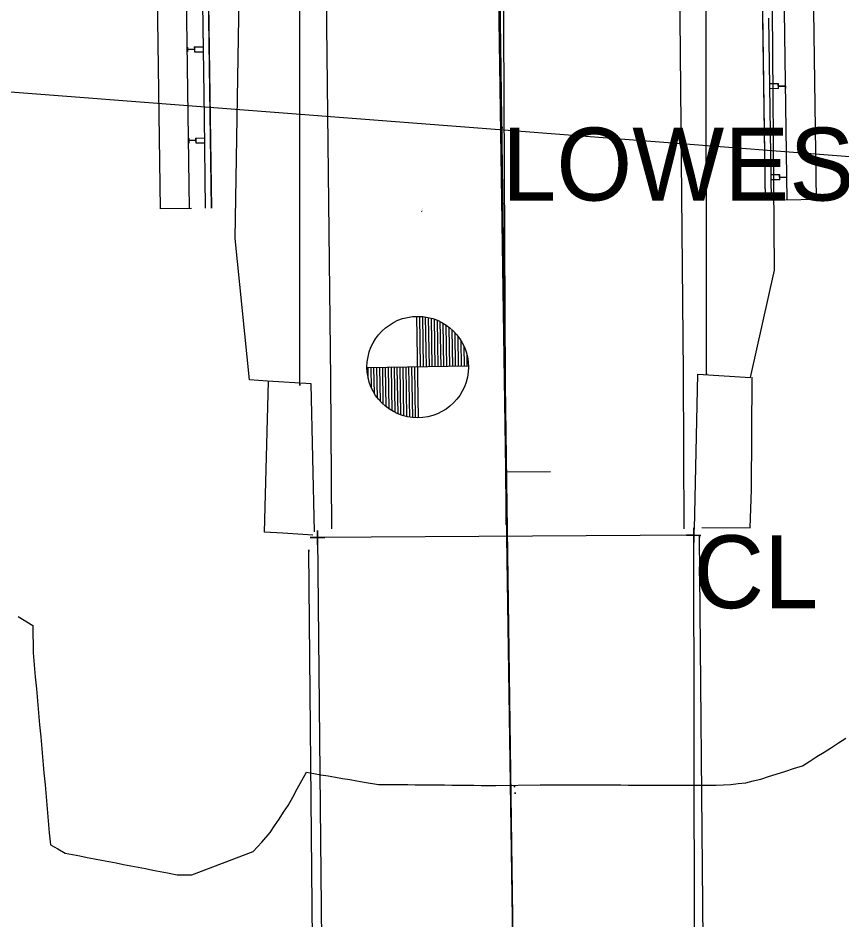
# Model space of a CAD drawing. Extents: x 1674300 to 1677920, y 225056 to 231852.
# Drawn here: x 1677341.1 to 1677397.6, y 229147 to 229208.9 of the extents above; entities that cross this region are included whole.
import ezdxf

# ---------------------------------------------------------------- set-up
doc = ezdxf.new("R2010")
doc.units = 0
for name, color, linetype in [('R_BoreHole', 7, 'Continuous'), ('R_Draft', 7, 'Continuous'), ('R_Horz Alg', 7, 'Continuous'), ('R_Horz Alg Annot', 7, 'Continuous'), ('R_No Plot', 7, 'Continuous'), ('R_Proposed Const Limits_Cut', 7, 'Continuous'), ('R_Proposed Road_Shoulder', 7, 'Continuous'), ('R_Steel', 7, 'Continuous'), ('S_BRIDGE', 7, 'Continuous'), ('S_BRIDGE_ANNOT', 7, 'Continuous'), ('S_EDGE_CONCRETE', 7, 'Continuous'), ('S_EDGE_PAVEMENT', 7, 'Continuous'), ('S_ELECTRIC_UTILITIES', 7, 'Continuous'), ('S_ELECTRIC_UTILITIES_ANNOT', 7, 'Continuous'), ('S_EXISTING_ALIGNMENT', 7, 'Continuous'), ('S_GUARDRAIL', 7, 'Continuous'), ('S_MSC_PT_SYM', 7, 'Continuous'), ('S_PAVEMENT_CROWN', 7, 'Continuous'), ('S_RDW_PT_SYM', 7, 'Continuous'), ('S_SHOULDER', 7, 'Continuous'), ('S_STR_PT_SYM', 7, 'Continuous'), ('S_UTL_PT_SYM', 7, 'Continuous')]:
    doc.layers.add(name, color=color, linetype=linetype)

msp = doc.modelspace()

# ---------------------------------------------------------------- linework, layer by layer
at = {"layer": 'R_BoreHole'}
for p, q in [((1677368.591, 229181.491), (1677368.475, 229188.447)), ((1677368.733, 229184.972), (1677368.675, 229188.451)), ((1677368.933, 229184.976), (1677368.876, 229188.431)), ((1677369.133, 229184.979), (1677369.076, 229188.405)), ((1677369.333, 229184.982), (1677369.277, 229188.367)), ((1677369.533, 229184.986), (1677369.478, 229188.317)), ((1677369.733, 229184.989), (1677369.679, 229188.254)), ((1677369.933, 229184.992), (1677369.88, 229188.176)), ((1677370.133, 229184.996), (1677370.082, 229188.084)), ((1677370.333, 229184.999), (1677370.283, 229187.975)), ((1677370.533, 229185.002), (1677370.486, 229187.848)), ((1677370.733, 229185.005), (1677370.688, 229187.7)), ((1677370.933, 229185.009), (1677370.891, 229187.527)), ((1677371.133, 229185.012), (1677371.094, 229187.323)), ((1677371.333, 229185.015), (1677371.298, 229187.079)), ((1677371.533, 229185.019), (1677371.503, 229186.78)), ((1677371.733, 229185.022), (1677371.71, 229186.386)), ((1677371.933, 229185.025), (1677371.92, 229185.761)), ((1677372.011, 229185.027), (1677365.055, 229184.911)), ((1677365.146, 229184.177), (1677365.133, 229184.913)), ((1677365.356, 229183.552), (1677365.333, 229184.916)), ((1677365.563, 229183.158), (1677365.533, 229184.919)), ((1677365.768, 229182.859), (1677365.733, 229184.923)), ((1677365.972, 229182.615), (1677365.933, 229184.926)), ((1677366.175, 229182.411), (1677366.133, 229184.929)), ((1677366.378, 229182.238), (1677366.333, 229184.933)), ((1677366.58, 229182.09), (1677366.533, 229184.936)), ((1677366.783, 229181.963), (1677366.733, 229184.939)), ((1677366.984, 229181.854), (1677366.933, 229184.942)), ((1677367.186, 229181.762), (1677367.133, 229184.946)), ((1677367.387, 229181.684), (1677367.333, 229184.949)), ((1677367.588, 229181.621), (1677367.533, 229184.952)), ((1677367.789, 229181.571), (1677367.733, 229184.956)), ((1677367.99, 229181.533), (1677367.933, 229184.959)), ((1677368.19, 229181.507), (1677368.133, 229184.962)), ((1677368.391, 229181.493), (1677368.333, 229184.966))]:
    msp.add_line(p, q, dxfattribs=at)
msp.add_circle((1677368.533, 229184.969), 3.479, dxfattribs=at)
at = {"layer": 'R_Horz Alg'}
msp.add_line((1677377.014, 229008.911), (1677360.581, 230177.652), dxfattribs=at)
at = {"layer": 'R_Horz Alg Annot'}
msp.add_lwpolyline([(1677377.64, 229177.793), (1677374.64, 229177.751)], dxfattribs=at)
at = {"layer": 'R_No Plot'}
for points in [[(1677392.38, 229196.403), (1677391.765, 229240.148), (1677391.304, 229415.159)], [(1677354.384, 229195.868), (1677353.768, 229239.614), (1677349.308, 229414.569)]]:
    msp.add_lwpolyline(points, dxfattribs=at)
at = {"layer": 'R_Proposed Const Limits_Cut'}
msp.add_lwpolyline([(1677341.122, 229167.849), (1677342.131, 229167.238), (1677342.139, 229166.613), (1677342.148, 229165.989), (1677342.157, 229165.364), (1677342.231, 229164.541), (1677342.305, 229163.718), (1677342.379, 229162.895), (1677342.453, 229162.072), (1677342.527, 229161.249), (1677342.601, 229160.426), (1677342.675, 229159.603), (1677342.749, 229158.78), (1677342.824, 229157.957), (1677342.898, 229157.134), (1677342.972, 229156.311), (1677343.046, 229155.488), (1677343.12, 229154.665), (1677343.194, 229153.842), (1677343.268, 229153.019), (1677343.342, 229152.196), (1677343.846, 229151.912), (1677344.35, 229151.628), (1677344.852, 229151.532), (1677345.353, 229151.435), (1677345.854, 229151.339), (1677346.356, 229151.242), (1677346.857, 229151.145), (1677347.359, 229151.049), (1677347.86, 229150.952), (1677348.361, 229150.856), (1677348.863, 229150.759), (1677349.364, 229150.662), (1677349.866, 229150.566), (1677350.367, 229150.469), (1677350.868, 229150.373), (1677351.37, 229150.276), (1677352.038, 229150.147), (1677352.541, 229150.14), (1677353.044, 229150.133), (1677357.258, 229151.733), (1677357.837, 229152.384), (1677358.416, 229153.035), (1677358.722, 229153.499), (1677359.028, 229153.963), (1677359.334, 229154.427), (1677359.64, 229154.891), (1677359.958, 229155.461), (1677360.276, 229156.031), (1677360.595, 229156.601), (1677360.913, 229157.171), (1677361.406, 229157.087), (1677361.9, 229157.003), (1677362.394, 229156.919), (1677362.887, 229156.835), (1677363.381, 229156.751), (1677363.874, 229156.668), (1677364.368, 229156.584), (1677364.862, 229156.5), (1677365.851, 229156.347), (1677366.353, 229156.342), (1677366.856, 229156.337), (1677367.359, 229156.332), (1677367.862, 229156.327), (1677368.365, 229156.322), (1677368.867, 229156.317), (1677369.37, 229156.312), (1677369.873, 229156.307), (1677370.376, 229156.302), (1677370.879, 229156.297), (1677371.382, 229156.292), (1677371.884, 229156.287), (1677372.387, 229156.282), (1677372.89, 229156.277), (1677373.393, 229156.272), (1677373.896, 229156.267), (1677376.922, 229156.317), (1677377.425, 229156.316), (1677377.928, 229156.314), (1677378.432, 229156.313), (1677378.935, 229156.312), (1677379.438, 229156.31), (1677379.941, 229156.309), (1677380.445, 229156.308), (1677380.948, 229156.306), (1677381.451, 229156.305), (1677381.954, 229156.303), (1677382.457, 229156.302), (1677382.961, 229156.301), (1677383.464, 229156.299), (1677383.967, 229156.298), (1677384.47, 229156.297), (1677384.974, 229156.295), (1677385.477, 229156.294), (1677385.98, 229156.293), (1677386.483, 229156.291), (1677386.987, 229156.29), (1677387.49, 229156.288), (1677387.993, 229156.287), (1677388.496, 229156.286), (1677389, 229156.284), (1677389.506, 229156.312), (1677390.013, 229156.339), (1677390.523, 229156.394), (1677391.032, 229156.45), (1677391.551, 229156.581), (1677392.07, 229156.711), (1677392.593, 229156.879), (1677393.116, 229157.047), (1677393.781, 229157.261), (1677394.303, 229157.428), (1677394.922, 229157.627), (1677395.418, 229157.938), (1677395.914, 229158.249), (1677396.409, 229158.564), (1677396.905, 229158.879), (1677397.401, 229159.194), (1677397.896, 229159.509)], dxfattribs=at)
at = {"layer": 'R_Proposed Road_Shoulder'}
for p, q in [((1677395.879, 229196.452), (1677393.755, 229196.422)), ((1677353.009, 229195.849), (1677350.884, 229195.819))]:
    msp.add_line(p, q, dxfattribs=at)
for points in [[(1677395.879, 229196.452), (1677395.264, 229240.197), (1677394.804, 229415.208), (1677394.663, 229425.207), (1677388.7, 229458.127)], [(1677350.884, 229195.819), (1677350.269, 229239.565), (1677345.809, 229414.519), (1677345.668, 229424.518), (1677350.704, 229457.592)]]:
    msp.add_lwpolyline(points, dxfattribs=at)
at = {"layer": 'R_Steel'}
for p, q in [((1677352.728, 229206.918), (1677352.744, 229206.918)), ((1677353.213, 229206.925), (1677353.228, 229206.925)), ((1677353.228, 229206.925), (1677353.811, 229206.933)), ((1677352.733, 229206.585), (1677352.749, 229206.585)), ((1677353.207, 229206.766), (1677352.754, 229206.759)), ((1677353.208, 229206.75), (1677352.755, 229206.743)), ((1677353.218, 229206.592), (1677353.233, 229206.592)), ((1677353.233, 229206.592), (1677353.816, 229206.6)), ((1677393.767, 229204.414), (1677393.751, 229204.413)), ((1677393.267, 229204.407), (1677392.684, 229204.398)), ((1677393.272, 229204.074), (1677392.689, 229204.065)), ((1677393.282, 229204.407), (1677393.267, 229204.407)), ((1677393.287, 229204.074), (1677393.272, 229204.074)), ((1677393.293, 229204.249), (1677393.746, 229204.255)), ((1677393.293, 229204.233), (1677393.746, 229204.239)), ((1677393.772, 229204.081), (1677393.756, 229204.08)), ((1677352.816, 229200.667), (1677352.832, 229200.668)), ((1677352.821, 229200.334), (1677352.837, 229200.335)), ((1677353.295, 229200.515), (1677352.842, 229200.509)), ((1677353.295, 229200.499), (1677352.842, 229200.493)), ((1677353.301, 229200.674), (1677353.316, 229200.674)), ((1677353.306, 229200.341), (1677353.321, 229200.341)), ((1677353.316, 229200.674), (1677353.899, 229200.683)), ((1677353.321, 229200.341), (1677353.904, 229200.35)), ((1677393.355, 229198.156), (1677392.772, 229198.148)), ((1677393.36, 229197.823), (1677392.777, 229197.815)), ((1677393.37, 229198.156), (1677393.355, 229198.156)), ((1677393.375, 229197.823), (1677393.36, 229197.823)), ((1677393.38, 229197.998), (1677393.833, 229198.005)), ((1677393.381, 229197.982), (1677393.834, 229197.989)), ((1677393.855, 229198.163), (1677393.839, 229198.163)), ((1677393.86, 229197.83), (1677393.844, 229197.83))]:
    msp.add_line(p, q, dxfattribs=at)
for points in [[(1677393.88, 229196.424), (1677393.265, 229240.169), (1677392.804, 229415.18)], [(1677352.884, 229195.847), (1677352.269, 229239.593), (1677347.808, 229414.547)], [(1677392.204, 229208.904), (1677392.116, 229215.154)], [(1677353.703, 229214.589), (1677353.791, 229208.34)], [(1677354.12, 229214.595), (1677354.208, 229208.345)], [(1677392.292, 229202.654), (1677392.204, 229208.903)], [(1677392.709, 229202.66), (1677392.621, 229208.909)], [(1677353.791, 229208.339), (1677353.879, 229202.089)], [(1677354.208, 229208.344), (1677354.296, 229202.095)], [(1677352.728, 229206.918), (1677352.733, 229206.585)], [(1677352.744, 229206.918), (1677352.746, 229206.767)], [(1677353.213, 229206.925), (1677353.215, 229206.774)], [(1677353.228, 229206.925), (1677353.233, 229206.592)], [(1677353.811, 229206.933), (1677353.816, 229206.6)], [(1677352.747, 229206.735), (1677352.749, 229206.585)], [(1677353.216, 229206.742), (1677353.218, 229206.592)], [(1677393.753, 229204.263), (1677393.751, 229204.413)], [(1677393.772, 229204.081), (1677393.767, 229204.414)], [(1677392.689, 229204.065), (1677392.684, 229204.398)], [(1677393.272, 229204.074), (1677393.267, 229204.407)], [(1677393.284, 229204.257), (1677393.282, 229204.407)], [(1677393.287, 229204.074), (1677393.285, 229204.225)], [(1677393.756, 229204.08), (1677393.754, 229204.231)], [(1677392.38, 229196.404), (1677392.292, 229202.653)], [(1677392.797, 229196.409), (1677392.709, 229202.659)], [(1677353.879, 229202.088), (1677353.967, 229195.862)], [(1677354.296, 229202.094), (1677354.383, 229195.868)], [(1677352.816, 229200.667), (1677352.821, 229200.334)], [(1677352.832, 229200.668), (1677352.834, 229200.517)], [(1677352.835, 229200.485), (1677352.837, 229200.335)], [(1677353.301, 229200.674), (1677353.303, 229200.523)], [(1677353.304, 229200.491), (1677353.306, 229200.341)], [(1677353.316, 229200.674), (1677353.321, 229200.341)], [(1677353.899, 229200.683), (1677353.904, 229200.35)], [(1677392.777, 229197.815), (1677392.772, 229198.148)], [(1677393.36, 229197.823), (1677393.355, 229198.156)], [(1677393.372, 229198.006), (1677393.37, 229198.156)], [(1677393.375, 229197.823), (1677393.373, 229197.974)], [(1677393.841, 229198.013), (1677393.839, 229198.163)], [(1677393.844, 229197.83), (1677393.842, 229197.981)], [(1677393.86, 229197.83), (1677393.855, 229198.163)]]:
    msp.add_lwpolyline(points, dxfattribs=at)
at = {"layer": 'S_BRIDGE'}
for p, q in [((1677387.463, 229173.43), (1677361.66, 229173.267)), ((1677361.66, 229173.267), (1677362.115, 229129.117)), ((1677387.554, 229129.116), (1677387.463, 229173.43))]:
    msp.add_line(p, q, dxfattribs=at)
at = {"layer": 'S_EDGE_CONCRETE'}
for points in [[(1677388.022, 229173.961), (1677391.331, 229173.938), (1677391.42, 229176.579), (1677391.466, 229184.266)], [(1677361.335, 229173.442), (1677359.285, 229173.569), (1677358.029, 229173.641), (1677358.299, 229183.986)]]:
    msp.add_lwpolyline(points, dxfattribs=at)
at = {"layer": 'S_EDGE_PAVEMENT'}
for points in [[(1677362.645, 229173.869), (1677362.584, 229184.136), (1677362.305, 229208.402), (1677362.026, 229232.669), (1677361.905, 229246.986), (1677361.784, 229261.304), (1677361.664, 229275.622), (1677361.543, 229289.939), (1677361.133, 229314.578), (1677360.723, 229339.217), (1677360.461, 229360.76), (1677360.199, 229382.303), (1677359.956, 229401.745), (1677359.713, 229421.186), (1677359.474, 229435.454), (1677359.235, 229449.723), (1677358.996, 229463.991)], [(1677386.817, 229173.866), (1677386.761, 229184.583), (1677386.536, 229208.922), (1677386.311, 229233.262), (1677386.168, 229247.359), (1677386.026, 229261.456), (1677385.883, 229275.554), (1677385.74, 229289.651), (1677385.381, 229314.626), (1677385.021, 229339.601), (1677384.739, 229361.36), (1677384.456, 229383.119), (1677384.197, 229401.897), (1677383.938, 229420.675), (1677383.771, 229435.189), (1677383.604, 229449.703), (1677383.437, 229464.216)]]:
    msp.add_lwpolyline(points, dxfattribs=at)
at = {"layer": 'S_ELECTRIC_UTILITIES'}
msp.add_line((1677541.682, 229188.351), (1677278.13, 229208.628), dxfattribs=at)
at = {"layer": 'S_EXISTING_ALIGNMENT'}
msp.add_line((1677375.224, 229134.426), (1677343.436, 231259.976), dxfattribs=at)
at = {"layer": 'S_GUARDRAIL'}
for p, q in [((1677360.449, 229183.748), (1677360.429, 229234.307)), ((1677388.336, 229184.481), (1677388.323, 229233.779)), ((1677388.275, 229129.172), (1677387.854, 229173.317)), ((1677361.48, 229129.268), (1677361.06, 229172.372))]:
    msp.add_line(p, q, dxfattribs=at)
at = {"layer": 'S_MSC_PT_SYM'}
for points in [[(1677374.326, 229201.392), (1677374.326, 229201.442), (1677374.326, 229201.392), (1677374.276, 229201.392), (1677374.326, 229201.392), (1677374.326, 229201.342), (1677374.326, 229201.392), (1677374.376, 229201.392)], [(1677375.172, 229156.201), (1677375.172, 229156.251), (1677375.172, 229156.201), (1677375.122, 229156.201), (1677375.172, 229156.201), (1677375.172, 229156.151), (1677375.172, 229156.201), (1677375.222, 229156.201)], [(1677375.223, 229155.747), (1677375.223, 229155.797), (1677375.223, 229155.747), (1677375.173, 229155.747), (1677375.223, 229155.747), (1677375.223, 229155.697), (1677375.223, 229155.747), (1677375.273, 229155.747)]]:
    msp.add_lwpolyline(points, dxfattribs=at)
at = {"layer": 'S_PAVEMENT_CROWN'}
msp.add_lwpolyline([(1677374.606, 229174.169), (1677374.538, 229188.801), (1677374.471, 229203.433), (1677374.403, 229218.065), (1677374.336, 229232.697), (1677374.165, 229246.992), (1677373.994, 229261.287), (1677373.823, 229275.582), (1677373.652, 229289.877), (1677373.306, 229314.835), (1677372.96, 229339.792), (1677372.861, 229361.139), (1677372.762, 229382.485), (1677372.341, 229401.685), (1677371.92, 229420.884), (1677371.716, 229435.359), (1677371.513, 229449.835), (1677371.309, 229464.31)], dxfattribs=at)
at = {"layer": 'S_RDW_PT_SYM'}
for points in [[(1677388.336, 229184.481), (1677388.336, 229184.531), (1677388.336, 229184.481), (1677388.286, 229184.481), (1677388.336, 229184.481), (1677388.336, 229184.431), (1677388.336, 229184.481), (1677388.386, 229184.481)], [(1677360.449, 229183.748), (1677360.449, 229183.798), (1677360.449, 229183.748), (1677360.399, 229183.748), (1677360.449, 229183.748), (1677360.449, 229183.698), (1677360.449, 229183.748), (1677360.499, 229183.748)], [(1677387.854, 229173.317), (1677387.854, 229173.367), (1677387.854, 229173.317), (1677387.804, 229173.317), (1677387.854, 229173.317), (1677387.854, 229173.267), (1677387.854, 229173.317), (1677387.904, 229173.317)], [(1677361.06, 229172.372), (1677361.06, 229172.422), (1677361.06, 229172.372), (1677361.01, 229172.372), (1677361.06, 229172.372), (1677361.06, 229172.322), (1677361.06, 229172.372), (1677361.11, 229172.372)]]:
    msp.add_lwpolyline(points, dxfattribs=at)
at = {"layer": 'S_SHOULDER'}
for points in [[(1677361.459, 229173.676), (1677361.218, 229183.826), (1677358.23, 229184.007), (1677356.989, 229184.092), (1677356.021, 229193.793), (1677356.329, 229213.087), (1677356.638, 229232.382), (1677356.363, 229246.75), (1677356.088, 229261.118), (1677355.813, 229275.487), (1677355.539, 229289.855), (1677355.061, 229314.395), (1677354.583, 229338.934), (1677355.008, 229360.449), (1677355.433, 229381.963), (1677355.692, 229401.783), (1677355.952, 229421.602), (1677355.753, 229435.774), (1677355.555, 229449.946), (1677355.357, 229464.117)], [(1677387.513, 229173.847), (1677387.751, 229184.486), (1677391.368, 229184.251), (1677393.008, 229191.615), (1677392.853, 229212.502), (1677392.698, 229233.389), (1677392.47, 229247.448), (1677392.242, 229261.507), (1677392.013, 229275.567), (1677391.785, 229289.626), (1677391.561, 229302.13), (1677391.337, 229314.633), (1677391.113, 229327.136), (1677390.889, 229339.64), (1677390.116, 229361.304), (1677389.342, 229382.968), (1677388.67, 229386.368), (1677387.978, 229403.516), (1677387.285, 229420.664), (1677387.124, 229435.165), (1677386.963, 229449.667), (1677386.801, 229464.168)]]:
    msp.add_lwpolyline(points, dxfattribs=at)
at = {"layer": 'S_STR_PT_SYM'}
for points in [[(1677361.66, 229173.267), (1677361.66, 229173.767), (1677361.66, 229173.267), (1677361.16, 229173.267), (1677361.66, 229173.267), (1677361.66, 229172.767), (1677361.66, 229173.267), (1677362.16, 229173.267)], [(1677387.463, 229173.43), (1677387.463, 229173.93), (1677387.463, 229173.43), (1677386.963, 229173.43), (1677387.463, 229173.43), (1677387.463, 229172.93), (1677387.463, 229173.43), (1677387.963, 229173.43)]]:
    msp.add_lwpolyline(points, dxfattribs=at)
at = {"layer": 'S_UTL_PT_SYM'}
msp.add_lwpolyline([(1677374.326, 229201.392), (1677374.326, 229201.442), (1677374.326, 229201.392), (1677374.276, 229201.392), (1677374.326, 229201.392), (1677374.326, 229201.342), (1677374.326, 229201.392), (1677374.376, 229201.392)], dxfattribs=at)

# ---------------------------------------------------------------- texts
at = {"layer": 'R_Draft'}
msp.add_text('B-1', height=0.12, rotation=90.94971, dxfattribs=at).set_placement((1677368.879, 229195.596))
at = {"layer": 'S_BRIDGE_ANNOT'}
msp.add_text('CL', height=5, rotation=360, dxfattribs=at).set_placement((1677387.463, 229168.43))
at = {"layer": 'S_ELECTRIC_UTILITIES_ANNOT'}
msp.add_text('LOWEST UTILITY LINE', height=5, rotation=360, dxfattribs=at).set_placement((1677374.326, 229196.392))

doc.saveas('drawing.dxf')
